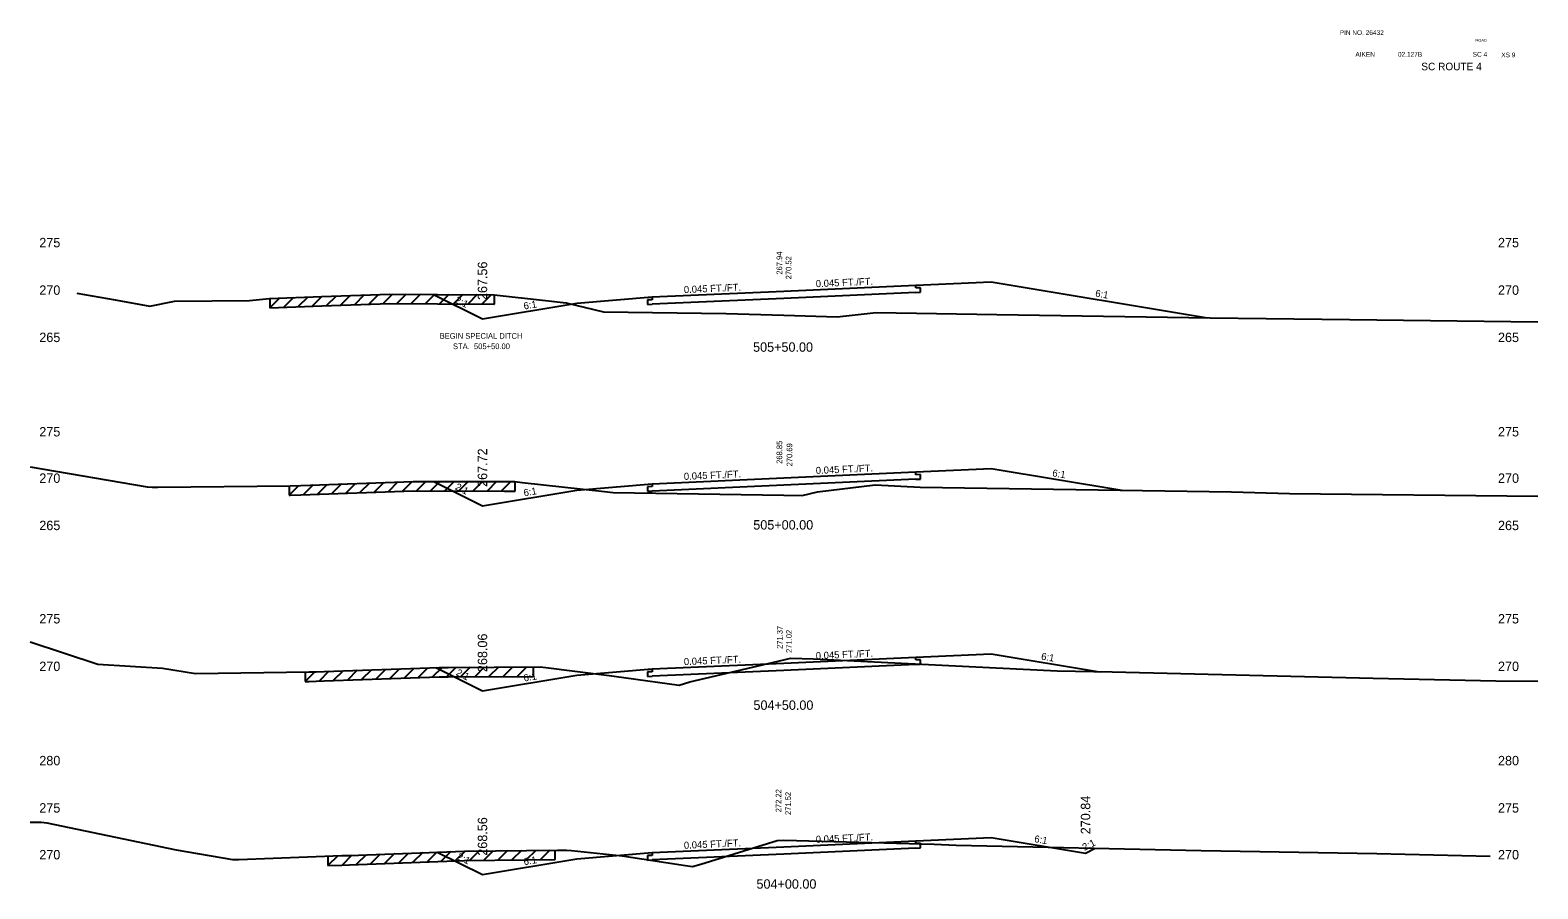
# Model space of a CAD drawing. Extents: x 883 to 1160, y 1002 to 4323.
# Drawn here: x 1000 to 1160, y 1932 to 2023.2 of the extents above; entities that cross this region are included whole.
import ezdxf

# ---------------------------------------------------------------- set-up
doc = ezdxf.new("R2010")
doc.units = 0
for name, color, linetype in [('Level 1', 7, 'Continuous'), ('Level 10', 7, 'Continuous'), ('Level 11', 7, 'Continuous'), ('Level 12', 7, 'Continuous'), ('Level 3', 7, 'Continuous'), ('Level 32', 7, 'Continuous'), ('Level 33', 7, 'Continuous'), ('Level 59', 7, 'Continuous'), ('Level 6', 7, 'Continuous'), ('Level 60', 7, 'Continuous'), ('Level 61', 7, 'Continuous'), ('Level 7', 7, 'Continuous')]:
    doc.layers.add(name, color=color, linetype=linetype)

msp = doc.modelspace()

# ---------------------------------------------------------------- linework, layer by layer
at = {"layer": 'Level 11'}
for p, q in [((1094, 1995.85), (1094, 1996.15)), ((1094.5, 1995.87), (1094, 1995.85)), ((1094, 1995.37), (1094.5, 1995.39)), ((1094.5, 1995.39), (1094.5, 1995.87)), ((1066, 1994.59), (1065.5, 1994.57)), ((1065.5, 1994.57), (1065.5, 1994.09)), ((1065.5, 1994.09), (1066, 1994.11)), ((1066, 1994.89), (1066, 1994.59)), ((1094, 1976.02), (1094, 1976.32)), ((1094.5, 1976.04), (1094, 1976.02)), ((1094.5, 1975.56), (1094.5, 1976.04)), ((1066, 1974.76), (1065.5, 1974.74)), ((1065.5, 1974.74), (1065.5, 1974.26)), ((1066, 1975.06), (1066, 1974.76)), ((1094, 1975.54), (1094.5, 1975.56)), ((1065.5, 1974.26), (1066, 1974.28)), ((1066, 1955.39), (1066, 1955.09)), ((1094, 1956.35), (1094, 1956.65)), ((1094.5, 1956.37), (1094, 1956.35)), ((1094, 1955.87), (1094.5, 1955.89)), ((1094.5, 1955.89), (1094.5, 1956.37)), ((1066, 1955.09), (1065.5, 1955.07)), ((1065.5, 1955.07), (1065.5, 1954.59)), ((1065.5, 1954.59), (1066, 1954.61)), ((1094, 1936.85), (1094, 1937.15)), ((1094.5, 1936.87), (1094, 1936.85)), ((1094, 1936.37), (1094.5, 1936.39)), ((1094.5, 1936.39), (1094.5, 1936.87)), ((1066, 1935.59), (1065.5, 1935.57)), ((1065.5, 1935.57), (1065.5, 1935.09)), ((1065.5, 1935.09), (1066, 1935.11)), ((1066, 1935.89), (1066, 1935.59))]:
    msp.add_line(p, q, dxfattribs=at)
at = {"layer": 'Level 12'}
for p, q in [((1094, 1995.37), (1080, 1994.74)), ((1080, 1994.74), (1066, 1994.11)), ((1080, 1974.91), (1066, 1974.28)), ((1094, 1975.54), (1080, 1974.91)), ((1080, 1955.24), (1066, 1954.61)), ((1094, 1955.87), (1080, 1955.24)), ((1094, 1936.37), (1080, 1935.74)), ((1080, 1935.74), (1066, 1935.11))]:
    msp.add_line(p, q, dxfattribs=at)
at = {"layer": 'Level 59'}
for p, q in [((1066, 1994.89), (1080, 1995.52)), ((1080, 1995.52), (1094, 1996.15)), ((1080, 1975.69), (1094, 1976.32)), ((1066, 1975.06), (1080, 1975.69)), ((1066, 1955.39), (1080, 1956.02)), ((1080, 1956.02), (1094, 1956.65)), ((1066, 1935.89), (1080, 1936.52)), ((1080, 1936.52), (1094, 1937.15))]:
    msp.add_line(p, q, dxfattribs=at)
at = {"layer": 'Level 6'}
for p, q in [((1094, 1996.15), (1102, 1996.51)), ((1058, 1994.22), (1066, 1994.89)), ((1094, 1976.32), (1102, 1976.68)), ((1058, 1974.39), (1066, 1975.06)), ((1094, 1956.65), (1102, 1957.01)), ((1058, 1954.72), (1066, 1955.39)), ((1094, 1937.15), (1102, 1937.51)), ((1058, 1935.22), (1066, 1935.89))]:
    msp.add_line(p, q, dxfattribs=at)
at = {"layer": 'Level 60'}
for p, q in [((1004.95, 1995.29), (1009.02, 1994.59)), ((1009.02, 1994.59), (1012.7, 1993.9)), ((1012.7, 1993.9), (1015.32, 1994.44)), ((1015.32, 1994.44), (1023.28, 1994.51)), ((1023.28, 1994.51), (1025.39, 1994.73)), ((1025.39, 1994.73), (1030.97, 1994.94)), ((1030.97, 1994.94), (1038.17, 1995.2)), ((1038.17, 1995.2), (1043.24, 1995.15)), ((1043.24, 1995.15), (1049.23, 1995.13)), ((1049.23, 1995.13), (1054.7, 1994.53)), ((1054.7, 1994.53), (1056.87, 1994.25)), ((1056.87, 1994.25), (1060.86, 1993.31)), ((1060.86, 1993.31), (1073.88, 1993.13)), ((1073.88, 1993.13), (1080, 1992.94)), ((1080, 1992.94), (1085.64, 1992.77)), ((1085.64, 1992.77), (1089.77, 1993.24)), ((1089.77, 1993.24), (1102.57, 1993.04)), ((1102.57, 1993.04), (1125.21, 1992.68)), ((1125.21, 1992.68), (1140.06, 1992.48)), ((1140.06, 1992.48), (1160, 1992.25)), ((1000, 1976.86), (1012.41, 1974.74)), ((1012.41, 1974.74), (1012.95, 1974.7)), ((1012.95, 1974.7), (1013.55, 1974.71)), ((1013.55, 1974.71), (1027.58, 1974.84)), ((1027.58, 1974.84), (1028.71, 1974.88)), ((1028.71, 1974.88), (1040.66, 1975.31)), ((1040.66, 1975.31), (1050.35, 1975.28)), ((1050.35, 1975.28), (1051.45, 1975.28)), ((1051.45, 1975.28), (1052.2, 1975.19)), ((1052.2, 1975.19), (1060.94, 1974.23)), ((1083.57, 1974.21), (1089.69, 1974.93)), ((1089.69, 1974.93), (1094.46, 1974.7)), ((1094.46, 1974.7), (1127.49, 1974.19)), ((1060.94, 1974.23), (1061.86, 1974.11)), ((1061.86, 1974.11), (1080, 1973.85)), ((1080, 1973.85), (1081.93, 1973.82)), ((1081.93, 1973.82), (1083.57, 1974.21)), ((1127.49, 1974.19), (1133.63, 1974.03)), ((1133.63, 1974.03), (1160, 1973.73)), ((1000, 1958.28), (1007.17, 1955.91)), ((1007.17, 1955.91), (1014.06, 1955.48)), ((1014.06, 1955.48), (1017.55, 1954.92)), ((1031.2, 1955.13), (1043.41, 1955.54)), ((1043.41, 1955.54), (1044.35, 1955.55)), ((1044.35, 1955.55), (1054.14, 1955.61)), ((1054.14, 1955.61), (1054.74, 1955.54)), ((1054.74, 1955.54), (1061.18, 1954.73)), ((1070, 1954.03), (1080, 1956.37)), ((1080, 1956.37), (1080.68, 1956.53)), ((1080.68, 1956.53), (1083.14, 1956.46)), ((1083.14, 1956.46), (1108.98, 1955.19)), ((1017.55, 1954.92), (1029.61, 1955.07)), ((1029.61, 1955.07), (1030.35, 1955.1)), ((1030.35, 1955.1), (1031.2, 1955.13)), ((1061.18, 1954.73), (1061.98, 1954.61)), ((1061.98, 1954.61), (1068.87, 1953.68)), ((1068.87, 1953.68), (1070, 1954.03)), ((1108.98, 1955.19), (1114.84, 1955.07)), ((1114.84, 1955.07), (1142.54, 1954.42)), ((1142.54, 1954.42), (1155.53, 1954.12)), ((1155.53, 1954.12), (1160, 1954.11)), ((1000, 1939.12), (1001.19, 1939.12)), ((1001.19, 1939.12), (1001.76, 1939.07)), ((1001.76, 1939.07), (1015.49, 1936.19)), ((1015.49, 1936.19), (1021.48, 1935.15)), ((1033.89, 1935.6), (1046.09, 1936.06)), ((1046.09, 1936.06), (1055.98, 1936.15)), ((1055.98, 1936.15), (1056.91, 1936.16)), ((1056.91, 1936.16), (1057.44, 1936.11)), ((1057.44, 1936.11), (1062.82, 1935.54)), ((1071.18, 1934.66), (1079.26, 1937.16)), ((1079.26, 1937.16), (1080, 1937.22)), ((1080, 1937.22), (1095.92, 1936.8)), ((1095.92, 1936.8), (1098.27, 1936.67)), ((1098.27, 1936.67), (1124.27, 1936.11)), ((1124.27, 1936.11), (1142.92, 1935.8)), ((1021.48, 1935.15), (1022.13, 1935.15)), ((1022.13, 1935.15), (1033.06, 1935.57)), ((1033.06, 1935.57), (1033.89, 1935.6)), ((1062.82, 1935.54), (1069.55, 1934.52)), ((1069.55, 1934.52), (1070.3, 1934.43)), ((1070.3, 1934.43), (1071.18, 1934.66)), ((1142.92, 1935.8), (1154.93, 1935.53))]:
    msp.add_line(p, q, dxfattribs=at)
at = {"layer": 'Level 61'}
for p, q in [((1026.46, 1994.77), (1025.42, 1993.73)), ((1025.42, 1994.73), (1025.42, 1993.73)), ((1025.42, 1993.73), (1030.97, 1993.94)), ((1027.96, 1994.83), (1026.92, 1993.79)), ((1029.46, 1994.88), (1028.42, 1993.84)), ((1030.96, 1994.94), (1029.92, 1993.9)), ((1030.97, 1993.94), (1038.17, 1994.2)), ((1032.46, 1994.99), (1031.42, 1993.95)), ((1033.96, 1995.04), (1032.93, 1994.01)), ((1035.46, 1995.1), (1034.43, 1994.06)), ((1036.97, 1995.15), (1035.93, 1994.12)), ((1038.45, 1995.19), (1037.43, 1994.17)), ((1038.17, 1994.2), (1043.24, 1994.15)), ((1039.92, 1995.18), (1038.93, 1994.19)), ((1041.42, 1995.17), (1040.43, 1994.18)), ((1042.92, 1995.15), (1041.93, 1994.16)), ((1043.24, 1994.15), (1049.23, 1994.13)), ((1044.43, 1995.15), (1043.43, 1994.15)), ((1045.93, 1995.14), (1044.93, 1994.15)), ((1047.43, 1995.14), (1046.43, 1994.14)), ((1048.93, 1995.13), (1047.94, 1994.13)), ((1049.23, 1994.13), (1049.28, 1994.13)), ((1049.28, 1994.13), (1049.28, 1995.13)), ((1028.52, 1974.87), (1027.49, 1973.84)), ((1027.49, 1974.84), (1027.49, 1973.84)), ((1030.03, 1974.93), (1028.99, 1973.89)), ((1031.53, 1974.98), (1030.49, 1973.94)), ((1033.03, 1975.03), (1031.99, 1974)), ((1034.53, 1975.09), (1033.49, 1974.05)), ((1036.03, 1975.14), (1034.99, 1974.11)), ((1037.53, 1975.2), (1036.49, 1974.16)), ((1039.03, 1975.25), (1038, 1974.21)), ((1040.53, 1975.31), (1039.5, 1974.27)), ((1041.99, 1975.31), (1041, 1974.31)), ((1043.49, 1975.3), (1042.5, 1974.3)), ((1044.99, 1975.29), (1044, 1974.3)), ((1046.49, 1975.29), (1045.5, 1974.29)), ((1048, 1975.28), (1047, 1974.29)), ((1049.5, 1975.28), (1048.5, 1974.28)), ((1051, 1975.28), (1050, 1974.28)), ((1051.47, 1974.28), (1051.47, 1975.28)), ((1027.49, 1973.84), (1027.58, 1973.84)), ((1027.58, 1973.84), (1028.71, 1973.88)), ((1028.71, 1973.88), (1040.66, 1974.31)), ((1040.66, 1974.31), (1050.35, 1974.28)), ((1050.35, 1974.28), (1051.45, 1974.28)), ((1051.45, 1974.28), (1051.47, 1974.28)), ((1034.71, 1955.25), (1033.67, 1954.21)), ((1036.21, 1955.3), (1035.18, 1954.27)), ((1037.71, 1955.35), (1036.68, 1954.32)), ((1039.21, 1955.4), (1038.18, 1954.37)), ((1040.72, 1955.45), (1039.68, 1954.42)), ((1042.22, 1955.5), (1041.18, 1954.47)), ((1043.71, 1955.55), (1042.68, 1954.52)), ((1045.19, 1955.56), (1044.18, 1954.55)), ((1046.69, 1955.57), (1045.68, 1954.56)), ((1048.19, 1955.57), (1047.19, 1954.57)), ((1049.69, 1955.58), (1048.69, 1954.58)), ((1051.19, 1955.59), (1050.19, 1954.58)), ((1052.7, 1955.6), (1051.69, 1954.59)), ((1053.4, 1954.6), (1053.4, 1955.6)), ((1030.2, 1955.09), (1029.17, 1954.07)), ((1029.17, 1955.07), (1029.17, 1954.07)), ((1029.17, 1954.07), (1029.61, 1954.07)), ((1029.61, 1954.07), (1030.35, 1954.1)), ((1030.35, 1954.1), (1031.2, 1954.13)), ((1031.71, 1955.15), (1030.67, 1954.11)), ((1031.2, 1954.13), (1043.41, 1954.54)), ((1033.21, 1955.2), (1032.17, 1954.16)), ((1043.41, 1954.54), (1044.35, 1954.55)), ((1044.35, 1954.55), (1053.4, 1954.6)), ((1044.66, 1936.01), (1043.62, 1934.97)), ((1046.16, 1936.06), (1045.12, 1935.02)), ((1047.64, 1936.07), (1046.63, 1935.07)), ((1049.14, 1936.09), (1048.13, 1935.08)), ((1050.64, 1936.1), (1049.63, 1935.09)), ((1052.15, 1936.11), (1051.13, 1935.11)), ((1053.65, 1936.13), (1052.64, 1935.12)), ((1055.15, 1936.14), (1054.14, 1935.13)), ((1055.71, 1935.15), (1055.71, 1936.15)), ((1032.65, 1935.55), (1031.6, 1934.51)), ((1031.6, 1935.51), (1031.6, 1934.51)), ((1031.6, 1934.51), (1033.06, 1934.57)), ((1033.06, 1934.57), (1033.89, 1934.6)), ((1034.15, 1935.61), (1033.11, 1934.57)), ((1033.89, 1934.6), (1046.09, 1935.06)), ((1035.65, 1935.67), (1034.61, 1934.63)), ((1037.15, 1935.73), (1036.11, 1934.69)), ((1038.65, 1935.78), (1037.61, 1934.74)), ((1040.16, 1935.84), (1039.12, 1934.8)), ((1041.66, 1935.89), (1040.62, 1934.86)), ((1043.16, 1935.95), (1042.12, 1934.91)), ((1046.09, 1935.06), (1055.71, 1935.15))]:
    msp.add_line(p, q, dxfattribs=at)
at = {"layer": 'Level 7'}
for p, q in [((1102, 1996.51), (1124.95, 1992.69)), ((1042.8, 1995.16), (1048, 1992.56)), ((1048, 1992.56), (1058, 1994.22)), ((1102, 1976.68), (1115.85, 1974.37)), ((1042.84, 1975.3), (1048, 1972.72)), ((1048, 1972.72), (1058, 1974.39)), ((1102, 1957.01), (1113.47, 1955.1)), ((1043.05, 1955.53), (1048, 1953.06)), ((1048, 1953.06), (1058, 1954.72)), ((1102, 1937.51), (1112, 1935.84)), ((1112, 1935.84), (1113.01, 1936.35)), ((1043.21, 1935.95), (1048, 1933.56)), ((1048, 1933.56), (1058, 1935.22))]:
    msp.add_line(p, q, dxfattribs=at)

# ---------------------------------------------------------------- texts
at = {"layer": 'Level 1'}
for s, height, p in [('PIN NO. 26432', 0.5, (1138.97, 2022.71)), ('AIKEN', 0.5, (1140.64, 2020.4)), ('02.127B', 0.5, (1145.15, 2020.4)), ('SC 4', 0.5, (1153.09, 2020.4)), ('XS 9', 0.5, (1156.12, 2020.34)), ('SC ROUTE 4', 0.8, (1147.63, 2018.96)), ('505+50.00', 1, (1076.72, 1989.07)), ('505+00.00', 1, (1076.74, 1970.19)), ('504+50.00', 1, (1076.76, 1951.05)), ('504+00.00', 1, (1077.08, 1932.06))]:
    msp.add_text(s, height=height, dxfattribs=at).set_placement(p)
at = {"layer": 'Level 10'}
for s, p in [('267.94', (1079.81, 1997.26)), ('268.85', (1079.81, 1977.17)), ('271.37', (1079.85, 1957.52)), ('272.22', (1079.72, 1940.17))]:
    msp.add_text(s, height=0.6, rotation=90, dxfattribs=at).set_placement(p)
at = {"layer": 'Level 3'}
for s, height, p in [('ROAD', 0.3, (1153.38, 2021.99)), (' 275', 1, (1000.6, 2000.16)), (' 275', 1, (1155.4, 2000.16)), (' 270', 1, (1000.6, 1995.12)), (' 270', 1, (1155.4, 1995.12)), (' 265', 1, (1000.6, 1990.1)), (' 265', 1, (1155.4, 1990.1)), (' 275', 1, (1000.6, 1980.08)), (' 275', 1, (1155.4, 1980.08)), (' 270', 1, (1000.6, 1975.15)), (' 270', 1, (1155.4, 1975.15)), (' 265', 1, (1000.6, 1970.13)), (' 265', 1, (1155.4, 1970.13)), (' 275', 1, (1000.6, 1960.22)), (' 275', 1, (1155.4, 1960.22)), (' 270', 1, (1000.6, 1955.17)), (' 270', 1, (1155.4, 1955.17)), (' 280', 1, (1000.6, 1945.16)), (' 280', 1, (1155.4, 1945.16)), (' 275', 1, (1000.6, 1940.14)), (' 275', 1, (1155.4, 1940.14)), (' 270', 1, (1000.6, 1935.17)), (' 270', 1, (1155.4, 1935.17))]:
    msp.add_text(s, height=height, dxfattribs=at).set_placement(p)
at = {"layer": 'Level 32'}
for s, rotation, p in [('0.045 FT./FT.', 2.5766, (1083.39, 1995.92)), ('0.045 FT./FT.', 2.5766, (1069.39, 1995.29)), ('6:1', 350.5377, (1112.99, 1994.93)), ('2:1', 333.435, (1045.01, 1994.33)), ('6:1', 9.4623, (1052.43, 1993.55)), ('0.045 FT./FT.', 2.5766, (1069.39, 1975.46)), ('0.045 FT./FT.', 2.5766, (1083.39, 1976.09)), ('6:1', 350.5377, (1108.44, 1975.86)), ('2:1', 333.435, (1045.03, 1974.49)), ('6:1', 9.4623, (1052.43, 1973.72)), ('0.045 FT./FT.', 2.5766, (1069.39, 1955.79)), ('0.045 FT./FT.', 2.5766, (1083.39, 1956.42)), ('6:1', 350.5377, (1107.25, 1956.39)), ('2:1', 333.435, (1045.13, 1954.77)), ('6:1', 9.4623, (1052.43, 1954.05)), ('0.045 FT./FT.', 2.5766, (1083.39, 1936.92)), ('6:1', 350.5377, (1106.52, 1937.01)), ('0.045 FT./FT.', 2.5766, (1069.39, 1936.29)), ('2:1', 26.5651, (1111.89, 1936.07)), ('2:1', 333.435, (1045.21, 1935.23)), ('6:1', 9.4623, (1052.43, 1934.55))]:
    msp.add_text(s, height=0.75, rotation=rotation, dxfattribs=at).set_placement(p)
for s, p in [('BEGIN SPECIAL DITCH', (1043.46, 1990.45)), ('STA.  505+50.00', (1044.87, 1989.35))]:
    msp.add_text(s, height=0.6, dxfattribs=at).set_placement(p)
at = {"layer": 'Level 33'}
for s, p in [('267.56', (1048.5, 1994.56)), ('267.72', (1048.5, 1974.72)), ('268.06', (1048.5, 1955.06)), ('270.84', (1112.5, 1937.84)), ('268.56', (1048.5, 1935.56))]:
    msp.add_text(s, height=1, rotation=90, dxfattribs=at).set_placement(p)
at = {"layer": 'Level 59'}
for s, p in [(' 270.52', (1080.79, 1996.54)), (' 270.69', (1080.88, 1976.68)), (' 271.02', (1080.83, 1956.87)), (' 271.52', (1080.73, 1939.66))]:
    msp.add_text(s, height=0.6, rotation=90, dxfattribs=at).set_placement(p)

doc.saveas('drawing.dxf')
